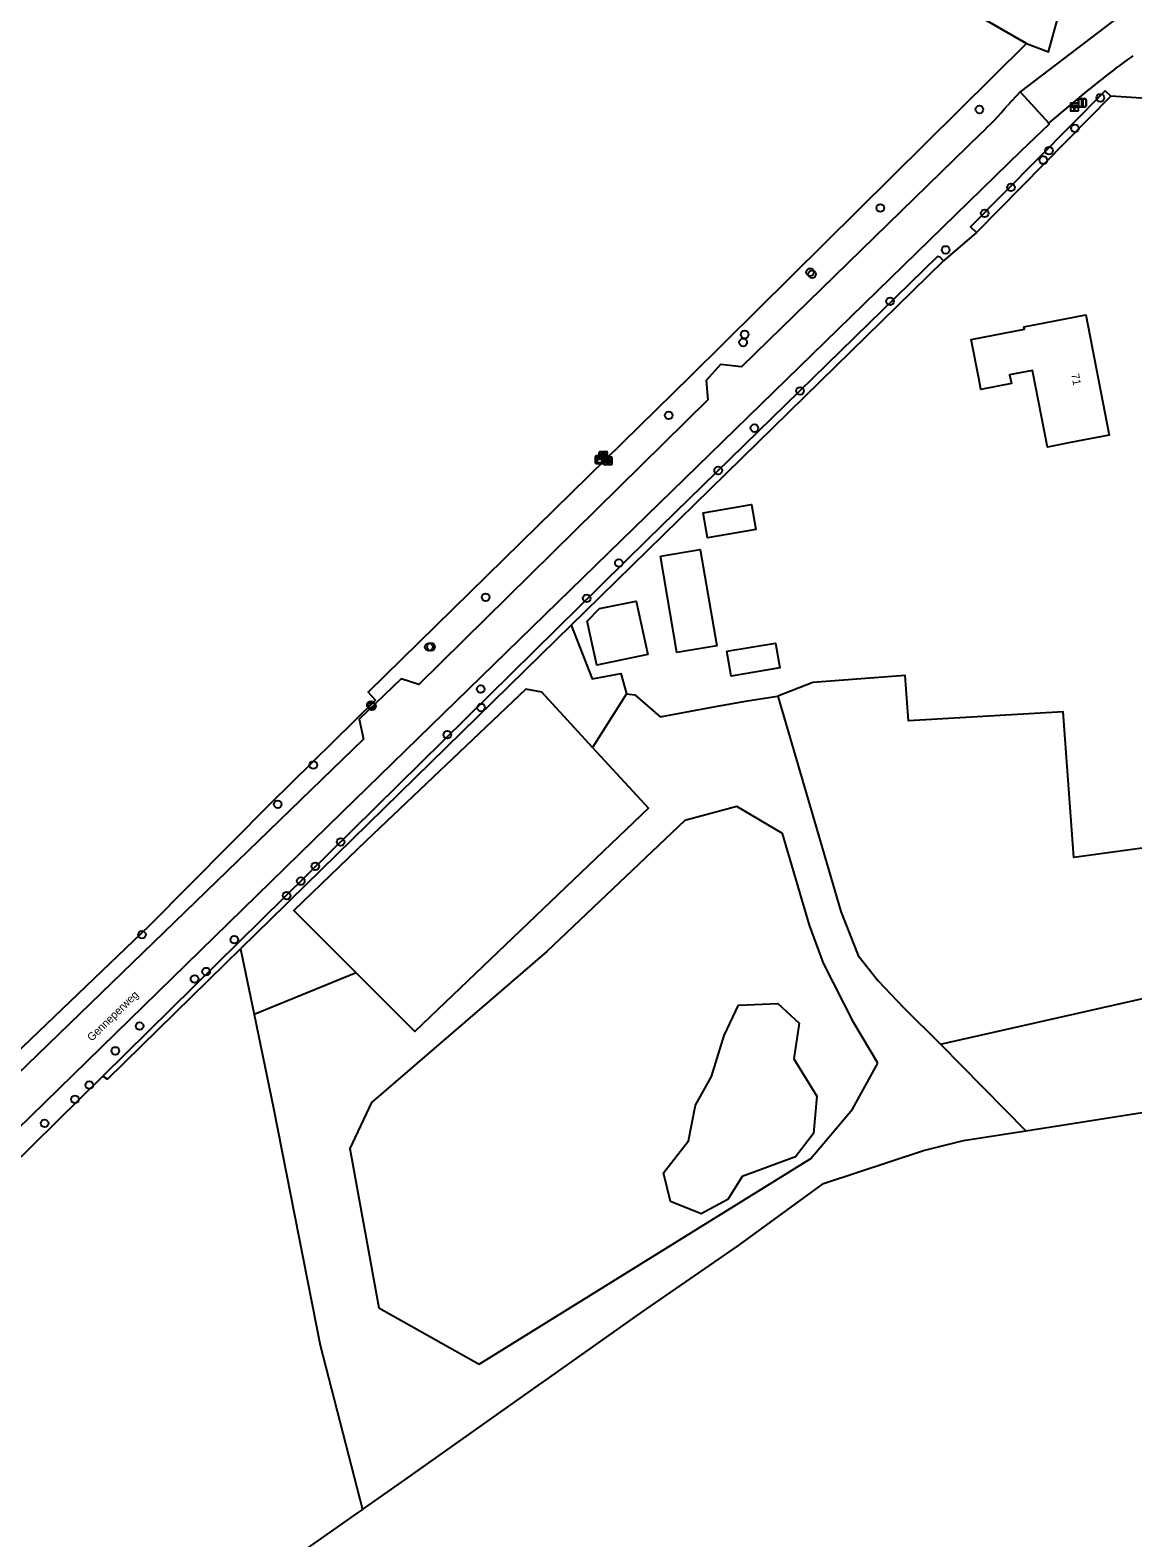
# Model space of a CAD drawing. Extents: x 160203 to 161526, y 379529 to 381797.
# Drawn here: x 160660 to 160799.8, y 380306.6 to 380497.8 of the extents above; entities that cross this region are included whole.
import ezdxf

# ---------------------------------------------------------------- set-up
doc = ezdxf.new("R2010")
doc.units = 0
for name, color, linetype in [('IMGEO_Boom', 7, 'Continuous'), ('IMGEO_Gemengd_bos', 7, 'Continuous'), ('IMGEO_Grasland_agrarisch', 7, 'Continuous'), ('IMGEO_Grasland_overig', 7, 'Continuous'), ('IMGEO_Hectometerpaal', 7, 'Continuous'), ('IMGEO_Hek', 7, 'Continuous'), ('IMGEO_Kast', 7, 'Continuous'), ('IMGEO_Loofbos', 7, 'Continuous'), ('IMGEO_Meer_plas_ven_vijver', 7, 'Continuous'), ('IMGEO_Openbare_ruimte_label', 7, 'Continuous'), ('IMGEO_Pand', 7, 'Continuous'), ('IMGEO_Pand_nummerreeks', 7, 'Continuous'), ('IMGEO_Rijbaan_lokaal_gesloten', 7, 'Continuous'), ('IMGEO_Rijbaan_lokaal_open', 7, 'Continuous'), ('IMGEO_Rioolput', 7, 'Continuous'), ('IMGEO_Terreindeel_onvherhard', 7, 'Continuous'), ('IMGEO_Verkeersbordpaal', 7, 'Continuous'), ('IMGEO_Waterloop', 7, 'Continuous')]:
    doc.layers.add(name, color=color, linetype=linetype)

msp = doc.modelspace()

# ---------------------------------------------------------------- linework, layer by layer
at = {"layer": 'IMGEO_Boom'}
for centre in [(160795.64, 380489.2), (160780.31, 380487.73), (160792.42, 380485.34), (160789.13, 380482.51), (160788.42, 380481.31), (160784.31, 380477.85), (160767.75, 380475.24), (160780.99, 380474.56), (160776.03, 380469.93), (160758.85, 380467.1), (160759.1, 380466.84), (160768.99, 380463.41), (160750.36, 380458.19), (160750.56, 380459.2), (160757.57, 380452.05), (160740.93, 380448.95), (160751.79, 380447.33), (160747.2, 380441.96), (160734.61, 380430.22), (160717.72, 380425.89), (160730.54, 380425.76), (160710.52, 380419.59), (160710.79, 380419.6), (160717.1, 380414.25), (160703.17, 380412.23), (160703.31, 380412.07), (160717.14, 380411.91), (160712.87, 380408.46), (160695.88, 380404.62), (160691.37, 380399.65), (160699.33, 380394.86), (160696.13, 380391.79), (160694.29, 380389.9), (160692.49, 380388.06), (160674.15, 380383.1), (160685.86, 380382.47), (160680.82, 380377.5), (160682.29, 380378.44), (160673.85, 380371.52), (160670.78, 380368.38), (160667.49, 380364.04), (160665.66, 380362.23), (160661.81, 380359.18)]:
    msp.add_circle(centre, 0.489, dxfattribs=at)
at = {"layer": 'IMGEO_Gemengd_bos'}
for points in [[(160786.21, 380358.26), (160807.9, 380361.66), (160818.58, 380363.9), (160826.41, 380365.96)], [(160702.13, 380310.25), (160707.47, 380313.99), (160724.41, 380325.98), (160725.08, 380326.45), (160737.54, 380335.26), (160749.78, 380343.69), (160760.53, 380351.56), (160773.23, 380355.77), (160773.89, 380355.93), (160778.28, 380357.01), (160785.11, 380358.08), (160786.21, 380358.26)], [(160702.13, 380310.25), (160701.49, 380309.8), (160678.19, 380293.45), (160671.98, 380289.38), (160664.52, 380285.1), (160656.59, 380280), (160645.5, 380272.28), (160628.77, 380260.1)]]:
    msp.add_lwpolyline(points, dxfattribs=at)
at = {"layer": 'IMGEO_Grasland_agrarisch'}
for points in [[(160488.28, 380202.97), (160500, 380213.96), (160536.75, 380250), (160569.66, 380282.2), (160629.02, 380340.26), (160630.62, 380341.83), (160648.01, 380358.08), (160657.08, 380367.01), (160675.12, 380384.28), (160690.5, 380399.79), (160703.76, 380412.84), (160702.84, 380413.86), (160743.68, 380453.92), (160786.3, 380496.09)], [(160775.37, 380369.23), (160814.31, 380378.03), (160810.82, 380395.45), (160792.3, 380392.89), (160790.93, 380411.37), (160771.32, 380410.23), (160770.88, 380415.99), (160759.18, 380415.09), (160754.77, 380413.37)], [(160754.77, 380413.37), (160762.76, 380386.03), (160764.96, 380380.47), (160767.46, 380377.26), (160770.7, 380373.9), (160775.37, 380369.23)], [(160767.42, 380366.84), (160764.38, 380371.95), (160760.56, 380379.51), (160758.77, 380384.3), (160755.35, 380395.95), (160749.57, 380399.36), (160742.98, 380397.57), (160725.49, 380380.97), (160703.27, 380361.84), (160700.5, 380355.99), (160704.17, 380335.8), (160716.89, 380328.66), (160758.93, 380354.75), (160764.22, 380360.99), (160767.42, 380366.84)], [(160688.36, 380372.98), (160690.81, 380361.12), (160696.74, 380331.08), (160702.13, 380310.25)]]:
    msp.add_lwpolyline(points, dxfattribs=at)
at = {"layer": 'IMGEO_Grasland_overig'}
for points in [[(160728.56, 380422.34), (160731.23, 380415.54), (160734.84, 380416.22), (160735.58, 380413.65)], [(160731.27, 380406.85), (160724.84, 380413.84), (160722.8, 380414.24), (160702.56, 380394.99), (160693.42, 380386.17), (160701.32, 380378.27)], [(160735.58, 380413.65), (160731.27, 380406.85)], [(160731.27, 380406.85), (160738.38, 380399.13), (160708.76, 380370.83), (160701.32, 380378.27)], [(160686.65, 380381.3), (160688.36, 380372.98)], [(160701.32, 380378.27), (160688.36, 380372.98)]]:
    msp.add_lwpolyline(points, dxfattribs=at)
at = {"layer": 'IMGEO_Hectometerpaal'}
for p, q in [((160791.86, 380488.45), (160791.86, 380487.61)), ((160791.86, 380488.45), (160791.86, 380487.61)), ((160792.77, 380488.54), (160791.93, 380488.54)), ((160792.77, 380488.54), (160791.93, 380488.54)), ((160792.86, 380487.62), (160792.86, 380488.46)), ((160792.86, 380487.62), (160792.86, 380488.46)), ((160791.94, 380487.54), (160792.78, 380487.54)), ((160791.94, 380487.54), (160792.78, 380487.54))]:
    msp.add_line(p, q, dxfattribs=at)
msp.add_lwpolyline([(160792.38, 380487.68), (160792.32, 380487.68), (160792.32, 380487.99), (160792.1, 380487.99), (160792.1, 380488.26), (160792.6, 380488.26), (160792.6, 380487.99), (160792.38, 380487.99), (160792.38, 380487.68)], dxfattribs=at)
for centre, start, end in [((160791.93, 380488.46), 92.4484, 184.2845), ((160791.93, 380488.46), 92.4484, 184.2845), ((160792.78, 380488.46), 2.4484, 94.2845), ((160792.78, 380488.46), 2.4484, 94.2845), ((160791.93, 380487.62), 182.4484, 274.2845), ((160791.93, 380487.62), 182.4484, 274.2845), ((160792.78, 380487.62), 272.4484, 4.2845), ((160792.78, 380487.62), 272.4484, 4.2845)]:
    msp.add_arc(centre, 0.0779, start, end, dxfattribs=at)
at = {"layer": 'IMGEO_Hek'}
msp.add_lwpolyline([(160766.96, 380507.35), (160779.54, 380500), (160786.3, 380496.09)], dxfattribs=at)
at = {"layer": 'IMGEO_Kast'}
for p, q in [((160731.65, 380442.9), (160731.65, 380443.74)), ((160731.65, 380443.74), (160731.65, 380442.9)), ((160731.72, 380443.83), (160732.56, 380443.83)), ((160732.56, 380443.83), (160731.72, 380443.83)), ((160732.57, 380442.83), (160731.73, 380442.83)), ((160731.73, 380442.83), (160732.57, 380442.83)), ((160732.65, 380443.75), (160732.65, 380442.91)), ((160732.65, 380442.91), (160732.65, 380443.75))]:
    msp.add_line(p, q, dxfattribs=at)
for points in [[(160731.84, 380443.62), (160732.44, 380443.62), (160732.44, 380443.53), (160731.84, 380443.53), (160731.84, 380443.62)], [(160731.84, 380443.44), (160732.44, 380443.44), (160732.44, 380442.95), (160731.84, 380442.95), (160731.84, 380443.44)]]:
    msp.add_lwpolyline(points, dxfattribs=at)
msp.add_circle((160731.93, 380443.29), 0.0377, dxfattribs=at)
for centre, start, end in [((160731.73, 380443.75), 92.4484, 184.2845), ((160731.73, 380443.75), 92.4484, 184.2845), ((160731.73, 380442.91), 182.4484, 274.2845), ((160731.73, 380442.91), 182.4484, 274.2845), ((160732.57, 380443.75), 2.4484, 94.2845), ((160732.57, 380443.75), 2.4484, 94.2845), ((160732.57, 380442.91), 272.4484, 4.2845), ((160732.57, 380442.91), 272.4484, 4.2845)]:
    msp.add_arc(centre, 0.0779, start, end, dxfattribs=at)
at = {"layer": 'IMGEO_Loofbos'}
for points in [[(160786.3, 380496.09), (160789.08, 380495.02), (160791.32, 380503.2), (160791.15, 380513.26), (160791.49, 380515.8), (160794.97, 380519.02), (160797.26, 380523.86), (160798.28, 380527.76), (160795.31, 380530.39), (160792.43, 380532.6), (160789.12, 380534.83), (160789.71, 380539.89), (160790.39, 380548.38), (160793.78, 380550.07), (160795.06, 380555.93), (160792.51, 380559.49)], [(160786.3, 380496.09), (160779.54, 380500), (160766.96, 380507.35)], [(160826.41, 380365.96), (160825.61, 380371.54), (160820.39, 380397.56), (160816.06, 380419.11), (160814.78, 380425.5), (160813.71, 380431.46), (160802.13, 380489.09), (160796.96, 380489.42)], [(160779.94, 380472.15), (160775.75, 380468.56)], [(160669.21, 380365.19), (160648.43, 380344.77), (160635.98, 380332.1), (160633.58, 380329.66), (160579.18, 380276.65)]]:
    msp.add_lwpolyline(points, dxfattribs=at)
at = {"layer": 'IMGEO_Meer_plas_ven_vijver'}
msp.add_lwpolyline([(160741.17, 380349.29), (160740.27, 380352.91), (160743.43, 380356.98), (160744.34, 380361.5), (160746.37, 380365.12), (160747.96, 380370.32), (160749.77, 380374.16), (160754.74, 380374.39), (160757.45, 380371.9), (160756.77, 380367.38), (160759.71, 380362.63), (160759.26, 380357.89), (160757, 380354.95), (160750.22, 380352.46), (160748.41, 380349.52), (160745.02, 380347.71), (160741.17, 380349.29)], dxfattribs=at)
at = {"layer": 'IMGEO_Pand'}
for points in [[(160780.23, 380453.66), (160779.27, 380458.56), (160786.02, 380459.88), (160785.96, 380460.16), (160793.81, 380461.69), (160796.77, 380446.46), (160791.87, 380445.51), (160788.93, 380444.93), (160787.04, 380454.65), (160784.14, 380454.09), (160784.36, 380452.97), (160780.51, 380452.22), (160780.23, 380453.66)], [(160745.3, 380436.59), (160751.43, 380437.65), (160751.97, 380434.5), (160745.83, 380433.43), (160745.3, 380436.59)], [(160739.89, 380431.1), (160744.91, 380431.93), (160747.02, 380419.73), (160741.95, 380418.88), (160739.89, 380431.1)], [(160738.28, 380418.64), (160731.8, 380417.28), (160730.58, 380422.84), (160732.17, 380424.45), (160736.79, 380425.39), (160738.28, 380418.64)], [(160748.31, 380419.04), (160754.46, 380420.09), (160755, 380416.93), (160748.85, 380415.89), (160748.31, 380419.04)]]:
    msp.add_lwpolyline(points, dxfattribs=at)
at = {"layer": 'IMGEO_Rijbaan_lokaal_gesloten'}
for points in [[(160798.06, 380499.57), (160785.49, 380489.98)], [(160789.09, 380486), (160794.28, 380490.3)], [(160785.49, 380489.98), (160789.09, 380486)]]:
    msp.add_lwpolyline(points, dxfattribs=at)
msp.add_arc((160843.31, 380432.13), 76.08, 124.9187, 130.1245, dxfattribs=at)
at = {"layer": 'IMGEO_Rijbaan_lokaal_open'}
for points in [[(160785.49, 380489.98), (160783.87, 380488.23)], [(160780.47, 380484.65), (160750.16, 380455.12), (160747.47, 380455.4), (160745.68, 380453.36), (160745.87, 380450.92), (160709.26, 380414.82), (160707.02, 380415.54), (160701.7, 380410.43), (160702.25, 380407.88), (160634.26, 380342.09), (160632.26, 380342.12), (160629.86, 380339.44), (160630.06, 380337.97), (160566.52, 380275.92), (160562.31, 380271.78), (160539.87, 380250), (160510.21, 380221.21)], [(160575.07, 380277.29), (160633.67, 380334.4), (160634.91, 380335.61), (160699.48, 380398.59), (160757.45, 380455.04), (160785.59, 380482.49), (160789.17, 380485.87), (160789.09, 380486)]]:
    msp.add_lwpolyline(points, dxfattribs=at)
msp.add_arc((160746.98, 380519.8), 48.55, 313.6067, 319.4426, dxfattribs=at)
at = {"layer": 'IMGEO_Rioolput'}
for p, q in [((160732.13, 380443.44), (160732.13, 380444.29)), ((160732.2, 380444.36), (160733.05, 380444.36)), ((160733.05, 380443.36), (160732.2, 380443.36)), ((160732.64, 380443.58), (160732.61, 380443.58)), ((160732.62, 380444.14), (160732.64, 380444.14)), ((160732.73, 380442.76), (160732.73, 380443.61)), ((160732.81, 380443.69), (160733.66, 380443.69)), ((160733.66, 380442.69), (160732.81, 380442.69)), ((160733.13, 380444.29), (160733.13, 380443.44)), ((160733.22, 380443.47), (160733.25, 380443.47)), ((160733.24, 380442.91), (160733.22, 380442.91)), ((160733.73, 380443.61), (160733.73, 380442.76))]:
    msp.add_line(p, q, dxfattribs=at)
for points in [[(160732.13, 380443.44), (160732.13, 380444.29)], [(160732.2, 380444.36), (160733.05, 380444.36)], [(160733.05, 380443.36), (160732.2, 380443.36)], [(160732.72, 380444.06), (160732.46, 380444.06), (160732.46, 380443.66)], [(160732.46, 380443.66), (160732.59, 380443.66), (160732.59, 380443.83), (160732.6, 380443.83)], [(160732.64, 380443.98), (160732.59, 380443.98), (160732.59, 380443.9)], [(160732.59, 380443.9), (160732.64, 380443.9)], [(160732.65, 380443.8), (160732.72, 380443.66), (160732.86, 380443.66), (160732.79, 380443.79)], [(160732.73, 380442.76), (160732.73, 380443.61)], [(160732.81, 380443.69), (160733.66, 380443.69)], [(160733.66, 380442.69), (160732.81, 380442.69)], [(160733.32, 380443.38), (160733.07, 380443.39), (160733.07, 380442.99)], [(160733.07, 380442.99), (160733.19, 380442.99), (160733.19, 380443.15), (160733.21, 380443.15)], [(160733.13, 380444.29), (160733.13, 380443.44)], [(160733.25, 380443.31), (160733.19, 380443.31), (160733.19, 380443.22)], [(160733.19, 380443.22), (160733.25, 380443.22)], [(160733.25, 380443.12), (160733.32, 380442.99), (160733.46, 380442.99), (160733.4, 380443.11)], [(160733.73, 380443.61), (160733.73, 380442.76)]]:
    msp.add_lwpolyline(points, dxfattribs=at)
for centre, radius, start, end in [((160732.2, 380444.29), 0.0765, 91.552, 178.448), ((160732.2, 380444.29), 0.0765, 91.552, 178.448), ((160732.2, 380443.44), 0.0765, 181.552, 268.448), ((160732.2, 380443.44), 0.0765, 181.552, 268.448), ((160732.6, 380443.77), 0.0533, 26.0293, 88.6989), ((160732.65, 380443.89), 0.0964, 77.0061, 93.1865), ((160732.62, 380444.09), 0.19, 274.7715, 282.9687), ((160732.66, 380443.94), 0.0378, 276.6634, 79.6772), ((160732.72, 380443.95), 0.109, 350.3612, 89.416), ((160732.71, 380443.95), 0.112, 277.5842, 350.9817), ((160732.7, 380443.74), 0.108, 29.5134, 73.7905), ((160732.81, 380443.61), 0.0765, 91.552, 178.448), ((160732.81, 380443.61), 0.0765, 91.552, 178.448), ((160732.81, 380442.76), 0.0765, 181.552, 268.448), ((160732.81, 380442.76), 0.0765, 181.552, 268.448), ((160733.05, 380444.29), 0.0765, 1.552, 88.448), ((160733.05, 380444.29), 0.0765, 1.552, 88.448), ((160733.05, 380443.44), 0.0765, 271.552, 358.448), ((160733.05, 380443.44), 0.0765, 271.552, 358.448), ((160733.2, 380443.1), 0.0533, 26.0293, 88.6989), ((160733.25, 380443.21), 0.0964, 77.0061, 93.1865), ((160733.23, 380443.41), 0.19, 274.7715, 282.9687), ((160733.27, 380443.27), 0.0378, 276.6634, 79.6772), ((160733.32, 380443.28), 0.109, 350.3612, 89.416), ((160733.32, 380443.27), 0.112, 277.5842, 350.9817), ((160733.3, 380443.06), 0.108, 29.5134, 73.7905), ((160733.66, 380443.61), 0.0765, 1.552, 88.448), ((160733.66, 380443.61), 0.0765, 1.552, 88.448), ((160733.66, 380442.76), 0.0765, 271.552, 358.448), ((160733.66, 380442.76), 0.0765, 271.552, 358.448)]:
    msp.add_arc(centre, radius, start, end, dxfattribs=at)
for centre, major_axis, ratio, start_param, end_param in [((160732.61, 380443.86), (-0.387, 0.002), 0.722429, 4.712389, 7.853982), ((160732.64, 380443.86), (-0.39, 0.002), 0.717154, 1.570796, 4.712389), ((160733.22, 380443.19), (-0.387, 0.002), 0.722429, 4.712389, 7.853982), ((160733.24, 380443.19), (-0.39, 0.002), 0.717154, 1.570796, 4.712389)]:
    msp.add_ellipse(centre, major_axis=major_axis, ratio=ratio, start_param=start_param, end_param=end_param, dxfattribs=at)
at = {"layer": 'IMGEO_Terreindeel_onvherhard'}
for points in [[(160735.58, 380413.65), (160736.65, 380413.5), (160739.83, 380410.72), (160746.87, 380412.02), (160750.92, 380412.76), (160754.17, 380413.28), (160754.77, 380413.37)], [(160775.37, 380369.23), (160778.06, 380366.54), (160786.21, 380358.26)]]:
    msp.add_lwpolyline(points, dxfattribs=at)
at = {"layer": 'IMGEO_Verkeersbordpaal'}
for p, q in [((160792.86, 380488.16), (160792.86, 380488.96)), ((160792.86, 380488.96), (160792.86, 380488.16)), ((160792.96, 380489.06), (160793.75, 380489.06)), ((160793.75, 380489.06), (160792.96, 380489.06)), ((160793.85, 380488.96), (160793.85, 380488.16)), ((160793.85, 380488.16), (160793.85, 380488.96)), ((160793.75, 380488.06), (160792.96, 380488.06)), ((160792.96, 380488.06), (160793.75, 380488.06))]:
    msp.add_line(p, q, dxfattribs=at)
msp.add_lwpolyline([(160793.28, 380488.94), (160793.43, 380488.94), (160793.43, 380488.19), (160793.28, 380488.19), (160793.28, 380488.94)], dxfattribs=at)
for centre, start, end in [((160792.96, 380488.96), 90, 180), ((160792.96, 380488.96), 90, 180), ((160793.75, 380488.96), 0, 90), ((160793.75, 380488.96), 360, 90), ((160792.96, 380488.16), 180, 270), ((160792.96, 380488.16), 180, 270), ((160793.75, 380488.16), 270, 0), ((160793.75, 380488.16), 270, 0)]:
    msp.add_arc(centre, 0.1, start, end, dxfattribs=at)
at = {"layer": 'IMGEO_Waterloop'}
for points in [[(160779.94, 380472.15), (160779.2, 380472.87), (160796.24, 380490.08), (160796.96, 380489.42)], [(160796.96, 380489.42), (160779.94, 380472.15)], [(160775.75, 380468.56), (160775.32, 380469), (160774.98, 380469.08), (160738.21, 380433.18), (160669.21, 380365.19)], [(160775.75, 380468.56), (160760.08, 380453.21), (160730.29, 380424.04), (160728.56, 380422.34)], [(160728.56, 380422.34), (160692.91, 380387.43), (160692.4, 380386.93), (160686.65, 380381.3)], [(160669.21, 380365.19), (160669.8, 380364.79), (160684.76, 380379.44), (160686.65, 380381.3)]]:
    msp.add_lwpolyline(points, dxfattribs=at)

# ---------------------------------------------------------------- texts
at = {"layer": 'IMGEO_Openbare_ruimte_label'}
msp.add_text('Genneperweg', height=1, rotation=44.2707, dxfattribs=at).set_placement((160667.79, 380369.53))
at = {"layer": 'IMGEO_Pand_nummerreeks'}
msp.add_text('71', height=1, rotation=281.0289, dxfattribs=at).set_placement((160791.94, 380454.15))

doc.saveas('drawing.dxf')
